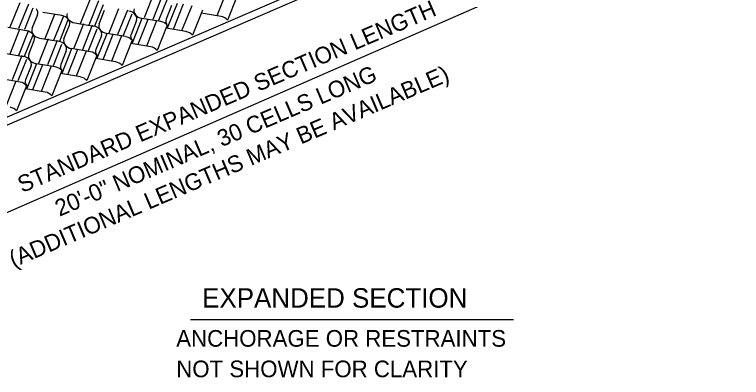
# Model space of a CAD drawing. Extents: x 638850 to 644908, y 297188 to 298900.
# Drawn here: x 639093.6 to 639224.8, y 298227.6 to 298293.1 of the extents above; entities that cross this region are included whole.
import ezdxf

# ---------------------------------------------------------------- set-up
doc = ezdxf.new("R2010")
doc.units = 0
for name, color, linetype in [('1', 7, 'Continuous'), ('2', 7, 'Continuous'), ('3', 7, 'Continuous'), ('6', 7, 'Continuous')]:
    doc.layers.add(name, color=color, linetype=linetype)

msp = doc.modelspace()

# ---------------------------------------------------------------- linework, layer by layer
at = {"layer": '2'}
for p, q in [((639118.75, 298296.84), (639116.99, 298292.45)), ((639131.93, 298297.39), (639130.12, 298292.85)), ((639107.21, 298295.79), (639105.45, 298291.39)), ((639108.78, 298295.53), (639107.02, 298291.13)), ((639120.33, 298296.58), (639118.57, 298292.18)), ((639121.14, 298295.87), (639119.6, 298292)), ((639133.87, 298296.6), (639132.05, 298292.06)), ((639094.55, 298295.18), (639092.79, 298290.78)), ((639096.12, 298294.92), (639094.36, 298290.52)), ((639096.94, 298294.21), (639095.39, 298290.34)), ((639109.6, 298294.82), (639108.05, 298290.95)), ((639112.41, 298294.12), (639110.65, 298289.72)), ((639121.97, 298294.7), (639120.98, 298292.22)), ((639122.96, 298295.06), (639121.19, 298290.63)), ((639124.04, 298294.92), (639122.22, 298290.38)), ((639125.59, 298294.66), (639123.77, 298290.12)), ((639097.76, 298293.03), (639096.77, 298290.56)), ((639102.15, 298292.87), (639098.73, 298293.45)), ((639100.86, 298293.06), (639099.1, 298288.66)), ((639102.44, 298292.8), (639100.68, 298288.4)), ((639108.88, 298291.39), (639109.87, 298293.86)), ((639113.99, 298293.85), (639112.23, 298289.45)), ((639114.8, 298293.14), (639113.25, 298289.27)), ((639127.53, 298293.87), (639125.71, 298289.33)), ((639130.88, 298292.72), (639127.31, 298293.32)), ((639103.25, 298292.09), (639101.71, 298288.22)), ((639104.49, 298291.55), (639107.91, 298290.97)), ((639115.63, 298291.97), (639114.64, 298289.49)), ((639116.62, 298292.34), (639114.85, 298287.9)), ((639117.7, 298292.2), (639115.88, 298287.66)), ((639120.01, 298291.8), (639116.6, 298292.38)), ((639119.25, 298291.93), (639117.43, 298287.39)), ((639095.8, 298290.14), (639092.39, 298290.72)), ((639094.52, 298290.34), (639092.76, 298285.94)), ((639102.53, 298288.66), (639103.52, 298291.14)), ((639106.07, 298291.39), (639104.31, 298286.99)), ((639107.64, 298291.13), (639105.88, 298286.73)), ((639108.46, 298290.42), (639106.91, 298286.55)), ((639121.18, 298291.15), (639119.37, 298286.61)), ((639124.54, 298289.99), (639120.96, 298290.6)), ((639096.1, 298290.07), (639094.34, 298285.67)), ((639096.91, 298289.36), (639095.36, 298285.49)), ((639098.15, 298288.82), (639101.57, 298288.25)), ((639109.29, 298289.24), (639108.29, 298286.77)), ((639110.28, 298289.61), (639108.5, 298285.17)), ((639111.35, 298289.47), (639109.54, 298284.93)), ((639113.67, 298289.08), (639110.25, 298289.66)), ((639112.9, 298289.21), (639111.09, 298284.67)), ((639096.19, 298285.93), (639097.18, 298288.41)), ((639099.72, 298288.66), (639097.96, 298284.26)), ((639101.3, 298288.4), (639099.54, 298284)), ((639102.11, 298287.69), (639100.57, 298283.82)), ((639114.84, 298288.42), (639113.02, 298283.88)), ((639118.2, 298287.26), (639114.62, 298287.87)), ((639102.94, 298286.51), (639101.95, 298284.04)), ((639103.93, 298286.88), (639102.16, 298282.45)), ((639105.01, 298286.74), (639103.19, 298282.2)), ((639107.33, 298286.35), (639103.91, 298286.93)), ((639106.56, 298286.48), (639104.74, 298281.94)), ((639091.8, 298286.1), (639095.22, 298285.52)), ((639094.96, 298285.67), (639093.2, 298281.27)), ((639095.77, 298284.96), (639094.22, 298281.09)), ((639108.5, 298285.69), (639106.68, 298281.15)), ((639111.85, 298284.54), (639108.28, 298285.14)), ((639096.6, 298283.79), (639095.61, 298281.31)), ((639097.59, 298284.15), (639095.82, 298279.72)), ((639098.67, 298284.02), (639096.85, 298279.47)), ((639100.98, 298283.62), (639097.57, 298284.2)), ((639100.22, 298283.75), (639098.4, 298279.21)), ((639102.15, 298282.96), (639100.34, 298278.43)), ((639105.51, 298281.81), (639101.93, 298282.42)), ((639094.64, 298280.9), (639091.22, 298281.48)), ((639093.87, 298281.03), (639092.06, 298276.49)), ((639095.81, 298280.24), (639093.99, 298275.7)), ((639099.17, 298279.08), (639095.59, 298279.69))]:
    msp.add_line(p, q, dxfattribs=at)
for centre, start_param, end_param in [((639096.26, 298293.55), 3.045062, 3.936083), ((639116.72, 298293.6), 6.186654, 7.077676), ((639102.02, 298291.65), 3.936083, 4.827105), ((639104.62, 298292.77), 6.186654, 7.077676), ((639114.12, 298292.48), 3.936083, 4.827105), ((639116.72, 298293.6), 0.794491, 1.685512), ((639114.12, 298292.48), 3.045062, 3.936083), ((639102.02, 298291.65), 3.045062, 3.936083), ((639104.62, 298292.77), 0.794491, 1.685512), ((639119.88, 298290.59), 3.936083, 4.827105), ((639122.48, 298291.71), 6.186654, 7.077676), ((639130.75, 298291.5), 3.936083, 4.827105), ((639095.67, 298288.92), 3.936083, 4.827105), ((639098.28, 298290.04), 6.186654, 7.077676), ((639107.78, 298289.76), 3.936083, 4.827105), ((639110.38, 298290.87), 6.186654, 7.077676), ((639107.78, 298289.76), 3.045062, 3.936083), ((639110.38, 298290.87), 0.794491, 1.685512), ((639095.67, 298288.92), 3.045062, 3.936083), ((639098.28, 298290.04), 0.794491, 1.685512), ((639113.54, 298287.86), 3.936083, 4.827105), ((639116.14, 298288.98), 6.186654, 7.077676), ((639124.41, 298288.77), 3.936083, 4.827105), ((639101.44, 298287.03), 3.936083, 4.827105), ((639104.04, 298288.15), 6.186654, 7.077676), ((639101.44, 298287.03), 3.045062, 3.936083), ((639104.04, 298288.15), 0.794491, 1.685512), ((639107.2, 298285.13), 3.936083, 4.827105), ((639109.8, 298286.25), 6.186654, 7.077676), ((639118.07, 298286.05), 3.936083, 4.827105), ((639095.09, 298284.3), 3.936083, 4.827105), ((639097.69, 298285.42), 6.186654, 7.077676), ((639097.69, 298285.42), 0.794491, 1.685512), ((639095.09, 298284.3), 3.045062, 3.936083), ((639100.85, 298282.41), 3.936083, 4.827105), ((639103.46, 298283.52), 6.186654, 7.077676), ((639111.72, 298283.32), 3.936083, 4.827105), ((639097.11, 298280.8), 6.186654, 7.077676), ((639105.38, 298280.59), 3.936083, 4.827105), ((639094.51, 298279.68), 3.936083, 4.827105), ((639099.04, 298277.87), 3.936083, 4.827105), ((639092.69, 298275.14), 3.936083, 4.827105)]:
    msp.add_ellipse(centre, major_axis=(-1.54, 0.4), ratio=0.764477, start_param=start_param, end_param=end_param, dxfattribs=at)
at = {"layer": '3'}
msp.add_line((639125.36, 298238.07), (639183.65, 298238.07), dxfattribs=at)
at = {"layer": '6'}
for p, q in [((639039.96, 298252.03), (639272.42, 298352.34)), ((639039.57, 298250.44), (639272.03, 298350.76)), ((639034.58, 298232.23), (639219.15, 298312.85))]:
    msp.add_line(p, q, dxfattribs=at)

# ---------------------------------------------------------------- texts
at = {"layer": '1'}
for s, p in [('ANCHORAGE OR RESTRAINTS', (639122.8, 298233.19)), ('NOT SHOWN FOR CLARITY', (639122.8, 298227.69))]:
    msp.add_text(s, height=3, dxfattribs=at).set_placement(p)
at = {"layer": '3'}
for s, p in [('STANDARD EXPANDED SECTION LENGTH', (639094.99, 298260.87)), ('(ADDITIONAL LENGTHS MAY BE AVAILABLE)', (639093.45, 298247.42)), ('20\'-0" NOMINAL, 30 CELLS LONG', (639101.73, 298256.61))]:
    msp.add_text(s, height=3, rotation=23.1871, dxfattribs=at).set_placement(p)
msp.add_text('EXPANDED SECTION', height=3.5, dxfattribs=at).set_placement((639127.47, 298240.23))

doc.saveas('drawing.dxf')
